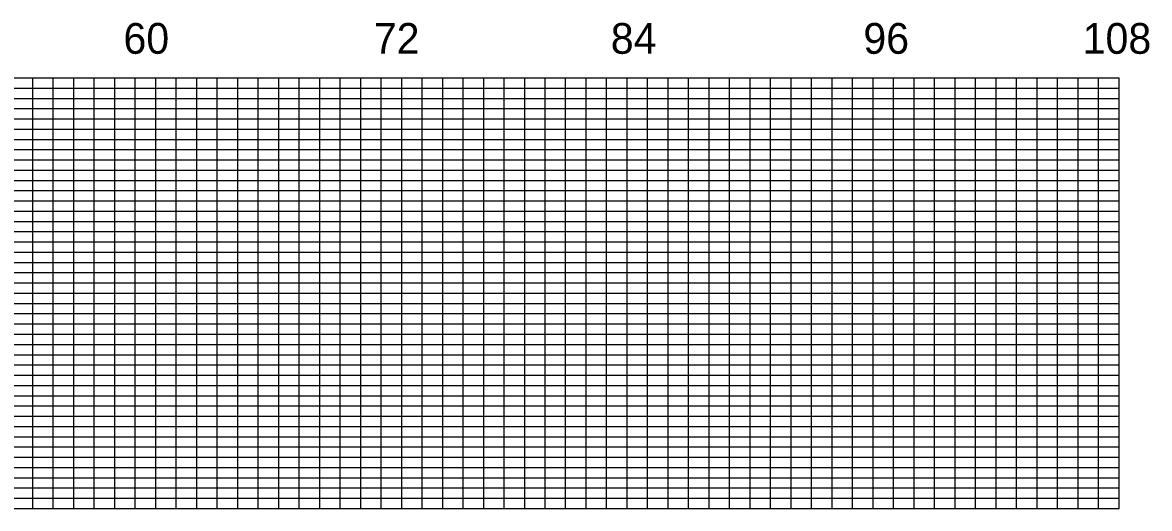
# Model space of a CAD drawing. Extents: x 1894907 to 1905782, y 740939 to 777025.
# Drawn here: x 1898307 to 1901056, y 760864 to 762049 of the extents above; entities that cross this region are included whole.
import ezdxf

# ---------------------------------------------------------------- set-up
doc = ezdxf.new("R2010")
doc.units = 0
doc.layers.add('RD_PD_WallFill', color=7, linetype='Continuous')

msp = doc.modelspace()

# ---------------------------------------------------------------- linework, layer by layer
at = {"layer": 'RD_PD_WallFill'}
for p, q in [((1895631.6, 761914.1), (1900981.6, 761914.1)), ((1898331.6, 760864.1), (1898331.6, 761914.1)), ((1898381.6, 760864.1), (1898381.6, 761914.1)), ((1898431.6, 760864.1), (1898431.6, 761914.1)), ((1898481.6, 760864.1), (1898481.6, 761914.1)), ((1898531.6, 760864.1), (1898531.6, 761914.1)), ((1898581.6, 760864.1), (1898581.6, 761914.1)), ((1898631.6, 760864.1), (1898631.6, 761914.1)), ((1898681.6, 760864.1), (1898681.6, 761914.1)), ((1898731.6, 760864.1), (1898731.6, 761914.1)), ((1898781.6, 760864.1), (1898781.6, 761914.1)), ((1898831.6, 760864.1), (1898831.6, 761914.1)), ((1898881.6, 760864.1), (1898881.6, 761914.1)), ((1898931.6, 760864.1), (1898931.6, 761914.1)), ((1898981.6, 760864.1), (1898981.6, 761914.1)), ((1899031.6, 760864.1), (1899031.6, 761914.1)), ((1899081.6, 760864.1), (1899081.6, 761914.1)), ((1899131.6, 760864.1), (1899131.6, 761914.1)), ((1899181.6, 760864.1), (1899181.6, 761914.1)), ((1899231.6, 760864.1), (1899231.6, 761914.1)), ((1899281.6, 760864.1), (1899281.6, 761914.1)), ((1899331.6, 760864.1), (1899331.6, 761914.1)), ((1899381.6, 760864.1), (1899381.6, 761914.1)), ((1899431.6, 760864.1), (1899431.6, 761914.1)), ((1899481.6, 760864.1), (1899481.6, 761914.1)), ((1899531.6, 760864.1), (1899531.6, 761914.1)), ((1899581.6, 760864.1), (1899581.6, 761914.1)), ((1899631.6, 760864.1), (1899631.6, 761914.1)), ((1899681.6, 760864.1), (1899681.6, 761914.1)), ((1899731.6, 760864.1), (1899731.6, 761914.1)), ((1899781.6, 760864.1), (1899781.6, 761914.1)), ((1899831.6, 760864.1), (1899831.6, 761914.1)), ((1899881.6, 760864.1), (1899881.6, 761914.1)), ((1899931.6, 760864.1), (1899931.6, 761914.1)), ((1899981.6, 760864.1), (1899981.6, 761914.1)), ((1900031.6, 760864.1), (1900031.6, 761914.1)), ((1900081.6, 760864.1), (1900081.6, 761914.1)), ((1900131.6, 760864.1), (1900131.6, 761914.1)), ((1900181.6, 760864.1), (1900181.6, 761914.1)), ((1900231.6, 760864.1), (1900231.6, 761914.1)), ((1900281.6, 760864.1), (1900281.6, 761914.1)), ((1900331.6, 760864.1), (1900331.6, 761914.1)), ((1900381.6, 760864.1), (1900381.6, 761914.1)), ((1900431.6, 760864.1), (1900431.6, 761914.1)), ((1900481.6, 760864.1), (1900481.6, 761914.1)), ((1900531.6, 760864.1), (1900531.6, 761914.1)), ((1900581.6, 760864.1), (1900581.6, 761914.1)), ((1900631.6, 760864.1), (1900631.6, 761914.1)), ((1900681.6, 760864.1), (1900681.6, 761914.1)), ((1900731.6, 760864.2), (1900731.6, 761914.1)), ((1900781.6, 760864.1), (1900781.6, 761914.1)), ((1900831.6, 760864.1), (1900831.6, 761914.1)), ((1900881.6, 760864.1), (1900881.6, 761914.1)), ((1900931.6, 760864.1), (1900931.6, 761914.1)), ((1900981.6, 760864.1), (1900981.6, 761914.1)), ((1896081.6, 761889.1), (1900981.6, 761889.1)), ((1896081.6, 761864.1), (1900981.6, 761864.1)), ((1896081.6, 761839.1), (1900981.6, 761839.1)), ((1896081.6, 761814.1), (1900981.6, 761814.1)), ((1895631.6, 761764.1), (1900981.6, 761764.1)), ((1896081.6, 761789.1), (1900981.6, 761789.1)), ((1895631.6, 761739.1), (1900981.6, 761739.1)), ((1895631.6, 761714.1), (1900981.6, 761714.1)), ((1895631.6, 761689.1), (1900981.6, 761689.1)), ((1895631.6, 761664.1), (1900981.6, 761664.1)), ((1895631.6, 761639.1), (1900981.6, 761639.1)), ((1895631.6, 761614.1), (1900981.6, 761614.1)), ((1895631.6, 761589.1), (1900981.6, 761589.1)), ((1895631.6, 761564.1), (1900981.6, 761564.1)), ((1895631.6, 761539.1), (1900981.6, 761539.1)), ((1895631.6, 761514.1), (1900981.6, 761514.1)), ((1895631.6, 761489.1), (1900981.6, 761489.1)), ((1895631.6, 761464.1), (1900981.6, 761464.1)), ((1895631.6, 761439.1), (1900981.6, 761439.1)), ((1895631.6, 761414.1), (1900981.6, 761414.1)), ((1895631.6, 761389.1), (1900981.6, 761389.1)), ((1895631.6, 761364.1), (1900981.6, 761364.1)), ((1895631.6, 761339.1), (1900981.6, 761339.1)), ((1895631.6, 761314.1), (1900981.6, 761314.1)), ((1895631.6, 761289.1), (1900981.6, 761289.1)), ((1895631.6, 761264.1), (1900981.6, 761264.1)), ((1895631.6, 761239.1), (1900981.6, 761239.1)), ((1895631.6, 761214.1), (1900981.6, 761214.1)), ((1895631.6, 761189.1), (1900981.6, 761189.1)), ((1895631.6, 761164.1), (1900981.6, 761164.1)), ((1895631.6, 761139.1), (1900981.6, 761139.1)), ((1895631.6, 761114.1), (1900981.6, 761114.1)), ((1895631.6, 761089.1), (1900981.6, 761089.1)), ((1895631.6, 761064.1), (1900981.6, 761064.1)), ((1895631.6, 761039.1), (1900981.6, 761039.1)), ((1895631.6, 761014.1), (1900981.6, 761014.1)), ((1895631.6, 760989.1), (1900981.6, 760989.1)), ((1895631.6, 760964.1), (1900981.6, 760964.1)), ((1895631.6, 760939.1), (1900981.6, 760939.1)), ((1895631.6, 760914.1), (1900981.6, 760914.1)), ((1895681.6, 760889.1), (1900981.6, 760889.1)), ((1895631.6, 760864.1), (1900981.6, 760864.1))]:
    msp.add_line(p, q, dxfattribs=at)

# ---------------------------------------------------------------- texts
for s, p in [('60', (1898552.8, 761972.8)), ('72', (1899163.5, 761972.8)), ('84', (1899741.7, 761972.8)), ('96', (1900357.8, 761972.8)), ('108', (1900892.8, 761972.8))]:
    msp.add_text(s, height=75, dxfattribs=at).set_placement(p)

doc.saveas('drawing.dxf')
